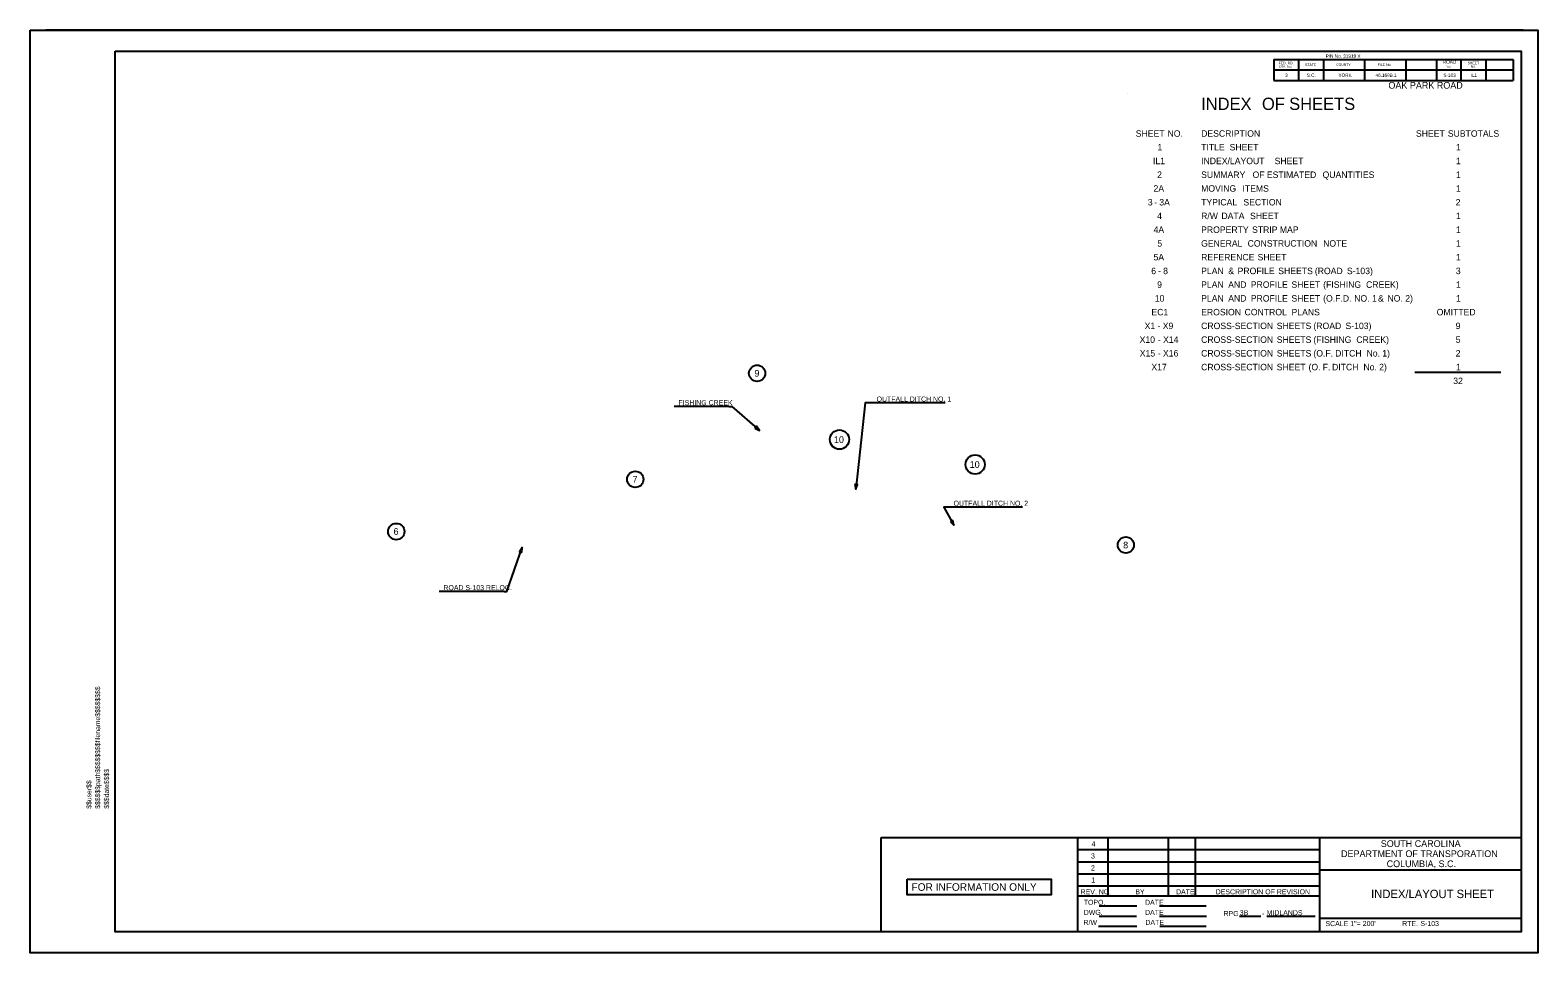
# Model space of a CAD drawing. Extents: x -796 to 2793, y -4650 to 4425.
# Drawn here: x 981 to 2777, y -125 to 975 of the extents above; entities that cross this region are included whole.
import ezdxf

# ---------------------------------------------------------------- set-up
doc = ezdxf.new("R2010")
doc.units = 0
for name, color, linetype in [('RD_HC_CL', 7, 'Continuous'), ('RD_HC_Data', 7, 'Continuous'), ('RD_HC_Data_Tic', 7, 'Continuous'), ('RD_SHT_Bndy', 7, 'Continuous'), ('RD_TX_Misc1', 7, 'Continuous')]:
    doc.layers.add(name, color=color, linetype=linetype)

msp = doc.modelspace()

# ---------------------------------------------------------------- linework, layer by layer
at = {"layer": 'RD_HC_CL'}
msp.add_lwpolyline([(981.4, 975), (2777.4, 975), (2777.4, -125), (981.4, -125)], close=True, dxfattribs=at)
at = {"layer": 'RD_HC_Data'}
for p, q in [((2760, 975), (1000, 975)), ((1000, 975), (2760, 975)), ((2463.1, 940), (2463.1, 915)), ((2463.1, 940), (2748.1, 940)), ((2492.1, 940), (2492.1, 915)), ((2522.1, 940), (2522.1, 915)), ((2571.1, 940), (2571.1, 915)), ((2620.1, 940), (2620.1, 915)), ((2656.6, 940), (2656.6, 915)), ((2685.6, 940), (2685.6, 915)), ((2715.6, 940), (2715.6, 915)), ((2748.1, 940), (2748.1, 915)), ((2463.1, 927.5), (2748.1, 927.5)), ((2288.9, 898.9), (2288.9, 898.9)), ((2463.1, 915), (2748.1, 915)), ((1995, 12.5), (2757.6, 12.5)), ((1995, -100), (1995, 12.5)), ((2229.6, -100), (2229.6, 12.5)), ((2229.6, 12.5), (2229.6, 12.5)), ((2265.6, -57.2), (2265.6, 12.5)), ((2337.6, -57.2), (2337.6, 12.5)), ((2369.4, -57.1), (2369.4, 12.5)), ((2517.6, -100), (2517.6, 12.5)), ((2229.6, -1.9), (2517.6, -1.9)), ((2229.6, -16.3), (2517.6, -16.3)), ((2229.6, -30.7), (2517.6, -30.7)), ((2517.6, -25.9), (2757.6, -25.9)), ((2229.6, -45.1), (2517.6, -45.1)), ((2229.6, -57.1), (2517.6, -57.1)), ((2255, -69.1), (2299.9, -69.1)), ((2326.8, -69.1), (2382.1, -69.1)), ((2255, -81.1), (2299.5, -81.1)), ((2326.8, -81.1), (2382.5, -81.1)), ((2422.1, -81.1), (2447.3, -81.1)), ((2454.5, -81.1), (2512, -81.1)), ((2517.6, -83.5), (2757.6, -83.5)), ((2254.2, -93.1), (2299.9, -93.1)), ((2327.2, -93.1), (2382.1, -93.1)), ((2760, -125), (1000, -125)), ((2760, -125), (1000, -125))]:
    msp.add_line(p, q, dxfattribs=at)
msp.add_lwpolyline([(1082.6, 950), (2757.6, 950), (2757.6, -100), (1082.6, -100)], close=True, dxfattribs=at)
at = {"layer": 'RD_HC_Data_Tic'}
msp.add_lwpolyline([(2026.3, -37), (2197.8, -37), (2197.8, -56), (2026.3, -56)], close=True, dxfattribs=at)
for centre, radius in [((1847.4, 565.9), 9.73), ((1945.5, 486.9), 11.5), ((2107.1, 457.2), 11.5), ((1702.2, 439.5), 9.72), ((1417.5, 377.3), 9.73), ((2286.6, 361.2), 9.67)]:
    msp.add_circle(centre, radius, dxfattribs=at)
at = {"layer": 'RD_SHT_Bndy'}
for p, q in [((2630.9, 567.2), (2733.3, 567.2)), ((1813.6, 526.4), (1748.7, 526.4)), ((2071.4, 530.7), (1984.7, 530.7)), ((2163.7, 406.5), (2076.4, 406.5)), ((1546.1, 305.9), (1468.7, 305.9))]:
    msp.add_line(p, q, dxfattribs=at)
for points in [[(1813.6, 526.4), (1817.1, 526.4), (1850.2, 497.8)], [(1984.7, 530.7), (1975.9, 530.7), (1964.9, 427.8)], [(2076.4, 406.5), (2069.8, 406.5), (2081.9, 384.7)], [(1546.1, 305.9), (1549.3, 305.9), (1567.6, 358.1)]]:
    msp.add_lwpolyline(points, dxfattribs=at)
for points in [[(1844.8, 500.4), (1850.2, 497.8), (1846.8, 502.7)], [(1963.9, 433.8), (1964.9, 427.8), (1967, 433.4)], [(2077.7, 389), (2081.9, 384.7), (2080.4, 390.5)], [(1567.2, 352.1), (1567.6, 358.1), (1564.2, 353.1)]]:
    msp.add_lwpolyline(points, close=True, dxfattribs=at)

# ---------------------------------------------------------------- texts
at = {"layer": 'RD_HC_Data_Tic'}
for s, height, p in [('FED. RD.', 3, (2468.7, 934.3)), ('STATE', 3, (2500.1, 932.3)), ('PIN No. 31919 X   ', 4, (2524.7, 942)), ('COUNTY', 3, (2537.1, 932.3)), ('FILE No.', 3, (2586.6, 932.3)), ('      ROAD      ', 4, (2655, 935.1)), ('SHEET', 3, (2693.7, 934.3)), ('DIV. No.', 3, (2469.3, 930.2)), ('3', 4, (2476.4, 919.3)), ('S.C.', 4, (2502.1, 919.3)), ('      YORK      ', 4, (2530.7, 919.3)), ('   46.169B.1    ', 4, (2579.4, 919.3)), ('     S-103      ', 4, (2657.2, 919.3)), ('No.', 3, (2667.9, 930.2)), ('      IL1       ', 4, (2688, 919.3)), ('No.', 3, (2697.4, 930.2)), ('OAK PARK ROAD                 ', 8, (2599.4, 905.2)), ('4', 6.24, (2245.8, 1.9)), ('SOUTH CAROLINA', 8, (2590.3, 1.2)), ('3', 6.24, (2245, -12.5)), ('DEPARTMENT OF TRANSPORATION', 8, (2543, -10.8)), ('COLUMBIA, S.C.', 8, (2597.3, -22.8)), ('2', 6.24, (2245, -26.9)), ('1', 6.24, (2245.4, -41.3)), ('FOR INFORMATION ONLY', 9, (2031.3, -51)), ('REV. NO.', 6, (2232.7, -55.2)), ('BY', 6, (2297.9, -55.2)), ('DATE', 6, (2346.4, -55.2)), ('DESCRIPTION OF REVISION', 6, (2393.7, -55.2)), ('      INDEX/LAYOUT SHEET       ', 10, (2556.5, -59.7)), ('TOPO.', 6, (2236.5, -67.7)), ('DATE', 6, (2309.5, -67.7)), ('R/W', 6, (2236.2, -91.7)), ('DWG.', 6, (2236.5, -79.7)), ('DATE', 6, (2309.5, -79.7)), ('DATE', 6, (2309.9, -91.7)), ('RPG', 6, (2403, -81.1)), ('3B    ', 6, (2422.3, -80.1)), ('-', 6, (2448.7, -81.1)), ('MIDLANDS   ', 6, (2454.3, -80.1)), ('SCALE 1"=', 6, (2524.4, -93.1)), ("200'       ", 6, (2568.8, -93)), ('RTE.', 6, (2615.8, -93.1)), ('S-103      ', 6, (2637.5, -93))]:
    msp.add_text(s, height=height, dxfattribs=at).set_placement(p)
at = {"layer": 'RD_SHT_Bndy'}
for s, height, p in [('INDEX', 14.7, (2376.3, 879.8)), (' OF', 14.7, (2443.3, 879.8)), (' SHEETS', 14.7, (2475.7, 879.8)), ('SHEET', 7.7, (2298.4, 847.9)), (' NO.', 7.7, (2333.4, 847.9)), ('DESCRIPTION', 7.7, (2376.3, 847.9)), ('SHEET', 7.7, (2632.2, 847.9)), (' SUBTOTALS', 7.7, (2667.3, 847.9)), ('1', 7.7, (2324.3, 831.6)), ('TITLE', 7.7, (2376.3, 831.6)), (' SHEET', 7.7, (2407.4, 831.6)), ('1', 7.7, (2679.9, 831.6)), ('IL1', 7.7, (2318.9, 815.2)), ('INDEX/LAYOUT', 7.7, (2376.3, 815.2)), (' SHEET', 7.7, (2461, 815.2)), ('1', 7.7, (2679.9, 815.2)), ('2', 7.7, (2323.9, 798.8)), ('SUMMARY', 7.7, (2376.3, 798.8)), (' OF', 7.7, (2434.7, 798.8)), (' ESTIMATED', 7.7, (2451.7, 798.8)), (' QUANTITIES', 7.7, (2518.1, 798.8)), ('1', 7.7, (2679.9, 798.8)), ('3', 7.7, (2312.8, 766)), ('2A', 7.7, (2319.6, 782.4)), (' 3A', 7.7, (2323.6, 766)), ('TYPICAL', 7.7, (2376.3, 766)), ('MOVING', 7.7, (2376.3, 782.4)), (' ITEMS', 7.7, (2422.7, 782.4)), (' SECTION', 7.7, (2423.8, 766)), ('2', 7.7, (2679.5, 766)), ('1', 7.7, (2679.9, 782.4)), (' -', 7.7, (2317.5, 766)), ('4', 7.7, (2323.9, 749.7)), ('R/W', 7.7, (2376.3, 749.7)), (' DATA', 7.7, (2397.6, 749.7)), (' SHEET', 7.7, (2431.7, 749.7)), ('1', 7.7, (2679.9, 749.7)), ('4A', 7.7, (2319.6, 733.3)), ('PROPERTY', 7.7, (2376.3, 733.3)), (' STRIP', 7.7, (2434.1, 733.3)), (' MAP', 7.7, (2467.2, 733.3)), ('1', 7.7, (2679.9, 733.3)), ('5', 7.7, (2324.1, 716.9)), ('GENERAL', 7.7, (2376.3, 716.9)), (' CONSTRUCTION', 7.7, (2428.8, 716.9)), (' NOTE', 7.7, (2518.8, 716.9)), ('1', 7.7, (2679.9, 716.9)), ('5A', 7.7, (2319.6, 700.5)), ('REFERENCE', 7.7, (2376.3, 700.5)), (' SHEET', 7.7, (2440.7, 700.5)), ('1', 7.7, (2679.9, 700.5)), ('6', 7.7, (2316.9, 684.1)), (' -', 7.7, (2322.1, 684.1)), (' 8', 7.7, (2328.2, 684.1)), ('PLAN', 7.7, (2376.3, 684.1)), (' &', 7.7, (2405.7, 684.1)), (' PROFILE', 7.7, (2416.9, 684.1)), (' SHEETS', 7.7, (2465.3, 684.1)), (' (ROAD', 7.7, (2508.9, 684.1)), (' S-103)', 7.7, (2547.1, 684.1)), ('3', 7.7, (2679.7, 684.1)), ('9', 7.7, (2323.9, 667.8)), ('PLAN', 7.7, (2376.3, 667.8)), (' AND', 7.7, (2405.7, 667.8)), (' PROFILE', 7.7, (2432.6, 667.8)), (' SHEET', 7.7, (2481, 667.8)), (' (FISHING', 7.7, (2518.8, 667.8)), (' CREEK)', 7.7, (2569.9, 667.8)), ('1', 7.7, (2679.9, 667.8)), ('10', 7.7, (2321.1, 651.4)), ('PLAN', 7.7, (2376.3, 651.4)), (' AND', 7.7, (2405.7, 651.4)), (' PROFILE', 7.7, (2432.6, 651.4)), (' SHEET', 7.7, (2481, 651.4)), (' (O.F.D.', 7.7, (2518.8, 651.4)), (' NO.', 7.7, (2555.8, 651.4)), (' 1', 7.7, (2577, 651.4)), (' &', 7.7, (2584.2, 651.4)), (' NO.', 7.7, (2595.4, 651.4)), (' 2)', 7.7, (2616.6, 651.4)), ('1', 7.7, (2679.9, 651.4)), ('EC1', 7.7, (2317.1, 635)), ('EROSION', 7.7, (2376.3, 635)), (' CONTROL', 7.7, (2425.2, 635)), (' PLANS', 7.7, (2481.1, 635)), ('OMITTED', 7.7, (2656.9, 635)), ('X1', 7.7, (2309, 618.6)), (' -', 7.7, (2321.6, 618.6)), (' X9', 7.7, (2327.7, 618.6)), ('CROSS-SECTION', 7.7, (2376.3, 618.6)), (' SHEETS', 7.7, (2463.5, 618.6)), (' (ROAD', 7.7, (2507.2, 618.6)), (' S-103)', 7.7, (2545.4, 618.6)), ('9', 7.7, (2679.5, 618.6)), ('X10', 7.7, (2303, 602.2)), ('X15', 7.7, (2303.2, 585.9)), (' -', 7.7, (2322, 602.2)), (' X16', 7.7, (2328, 585.9)), (' X14', 7.7, (2328.1, 602.2)), ('CROSS-SECTION', 7.7, (2376.3, 602.2)), ('CROSS-SECTION', 7.7, (2376.3, 585.9)), (' SHEETS', 7.7, (2463.5, 602.2)), (' SHEETS', 7.7, (2463.5, 585.9)), (' (FISHING', 7.7, (2507.2, 602.2)), (' (O.F.', 7.7, (2507.2, 585.9)), (' DITCH', 7.7, (2533.1, 585.9)), (' CREEK)', 7.7, (2558.3, 602.2)), (' No.', 7.7, (2570.5, 585.9)), (' 1)', 7.7, (2589.2, 585.9)), ('5', 7.7, (2679.6, 602.2)), ('2', 7.7, (2679.5, 585.9)), ('X17', 7.7, (2317, 569.5)), (' -', 7.7, (2321.9, 585.9)), ('CROSS-SECTION', 7.7, (2376.3, 569.5)), (' SHEET', 7.7, (2463.5, 569.5)), (' (O.', 7.7, (2501.4, 569.5)), (' F.', 7.7, (2518.2, 569.5)), (' DITCH', 7.7, (2529.4, 569.5)), (' No.', 7.7, (2566.8, 569.5)), (' 2)', 7.7, (2585.5, 569.5)), ('1', 7.7, (2679.9, 569.5)), ('9', 8, (1844.2, 561.9)), ('32', 7.7, (2676.6, 553.1)), ('FISHING CREEK', 6, (1753.7, 527.9)), ('OUTFALL DITCH NO. 1', 6, (1989.7, 532.2)), ('10', 8, (1938.9, 482.9)), ('10', 8, (2100.6, 453.2)), ('7', 8, (1699, 435.5)), ('OUTFALL DITCH NO. 2', 6, (2081.4, 408)), ('6', 8, (1414.3, 373.3)), ('8', 8, (2283.4, 357.2)), ('ROAD S-103 RELOC.', 6, (1473.7, 307.4))]:
    msp.add_text(s, height=height, dxfattribs=at).set_placement(p)
at = {"layer": 'RD_TX_Misc1'}
for s, p in [('$$$$$$path$$$$$$$$filename$$$$$$$$', (1064.8, 46.8)), ('$$$date$$$$', (1075.3, 46.8)), ('$$user$$', (1054.3, 46.8))]:
    msp.add_text(s, height=5.88, rotation=90, dxfattribs=at).set_placement(p)

doc.saveas('drawing.dxf')
